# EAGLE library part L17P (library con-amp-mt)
AMP MT CONNECTOR
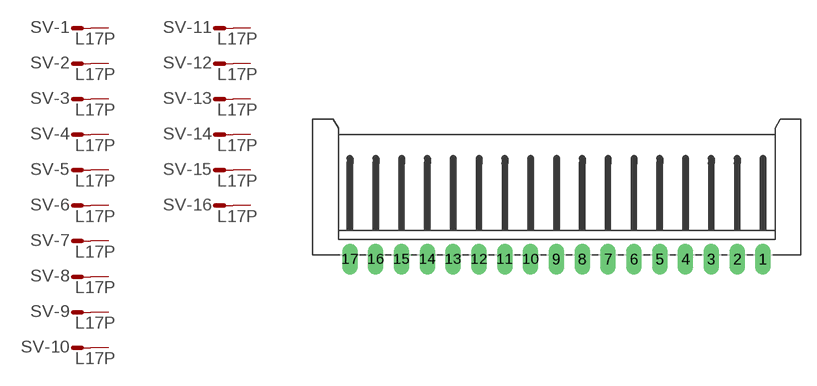
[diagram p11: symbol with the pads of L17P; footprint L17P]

Designator prefix SV; gates -1=M -2=M -3=M -4=M -5=M -6=M -7=M -8=M -9=M -10=M -11=M -12=M -13=M -14=M -15=M -16=M -17=M

## L17P (OC_FARNELL: unknown; OC_NEWARK: unknown)  [L17P]
1  -1:S  pas
2  -2:S  pas
3  -3:S  pas
4  -4:S  pas
5  -5:S  pas
6  -6:S  pas
7  -7:S  pas
8  -8:S  pas
9  -9:S  pas
10  -10:S  pas
11  -11:S  pas
12  -12:S  pas
13  -13:S  pas
14  -14:S  pas
15  -15:S  pas
16  -16:S  pas
17  -17:S  pas

## Footprint L17P (pad centres in mm)
AMP MT CONNECTOR
drill 1.016 long: 1 20,-6.25; 2 17.5,-6.25; 3 15,-6.25; 4 12.5,-6.25; 5 10,-6.25; 6 7.5,-6.25; 7 5,-6.25; 8 2.5,-6.25; 9 0,-6.25; 10 -2.5,-6.25; 11 -5,-6.25; 12 -7.5,-6.25; 13 -10,-6.25; 14 -12.5,-6.25; 15 -15,-6.25; 16 -17.5,-6.25; 17 -20,-6.25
